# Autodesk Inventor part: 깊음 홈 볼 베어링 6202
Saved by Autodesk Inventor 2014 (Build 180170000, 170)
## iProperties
Created: 2024-11
Part Number: 깊음 홈 볼 베어링 6202
Material: 일반
Document SubType Name: Modeling
Designer: dg
Density: 1 g/cm^3
Appearance: 기본값
Author: dg
Author: jhkim
Description: 깊은 그루브 볼 베어링
Creation Date: 2024-10-25
Sending System: Autodesk Inventor 2025
Preprocessor: ST-DEVELOPER v20
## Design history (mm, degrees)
node "깊음 홈 볼 베어링 62021"
body "Solid1"
node "Solid1_1"
node "Solid1_2"
node "Solid1_3"
node "Solid1_4"
node "Solid1_5"
node "Solid1_6"
node "Solid1_7"
node "Solid1_8"
node "Solid1_9"
node "기준1"
node "기준2"
node "기준3"
node "기준4"
node "기준5"
node "기준6"
node "기준7"
node "기준8"
node "기준9"
node "기준10"
